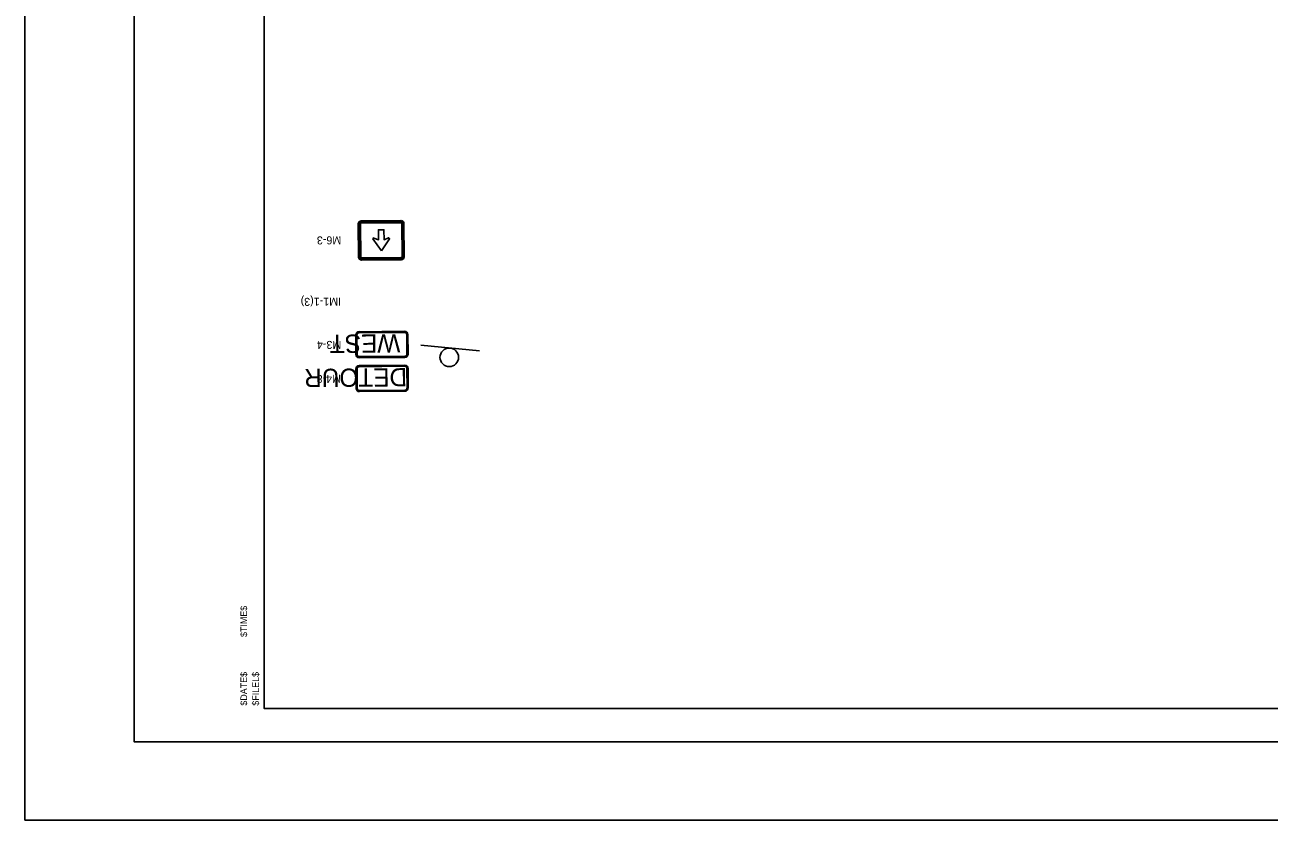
# Model space of a CAD drawing. Extents: x 2162123 to 2216123, y 180770 to 216770.
# Drawn here: x 2162123 to 2190113, y 180770 to 198666 of the extents above; entities that cross this region are included whole.
import ezdxf

# ---------------------------------------------------------------- set-up
doc = ezdxf.new("R2010")
doc.units = 0
for name, color, linetype in [('Default', 7, 'Continuous'), ('PR_Phasing_Detour_1', 7, 'Continuous'), ('SHT_Plot_Shape_Full', 7, 'Continuous'), ('SHT_Plot_Shape_Half', 7, 'Continuous'), ('SHT_Plot_Stamp', 7, 'Continuous'), ('SHT_Section_Layout_Block', 7, 'Continuous'), ('SHT_Sheet_Border', 7, 'Continuous')]:
    doc.layers.add(name, color=color, linetype=linetype)

# ---------------------------------------------------------------- blocks, each defined once
blk = doc.blocks.new('PRSIGN')
at = {"layer": 'Default'}
blk.add_line((20.04, 6.36), (-20.04, 6.36), dxfattribs=at)
blk.add_circle((0, 0), 6.35, dxfattribs=at)

msp = doc.modelspace()

# ---------------------------------------------------------------- linework, layer by layer
at = {"layer": 'PR_Phasing_Detour_1'}
for p, q in [((2170584, 194261), (2169689, 194253)), ((2169624, 194188), (2169630, 193439)), ((2169643, 194188), (2169649, 193439)), ((2169643, 194188), (2169649, 193439)), ((2169679, 193439), (2169673, 194188)), ((2169679, 193439), (2169673, 194188)), ((2170585, 194242), (2169689, 194235)), ((2170585, 194242), (2169689, 194235)), ((2169689, 194205), (2170585, 194212)), ((2169689, 194205), (2170585, 194212)), ((2170201, 194056), (2170076, 194055)), ((2170076, 194055), (2170078, 193829)), ((2170202, 193830), (2170201, 194056)), ((2170601, 194196), (2170607, 193447)), ((2170601, 194196), (2170607, 193447)), ((2170638, 193447), (2170632, 194196)), ((2170638, 193447), (2170632, 194196)), ((2170656, 193447), (2170650, 194196)), ((2169953, 193849), (2170142, 193579)), ((2170078, 193829), (2169973, 193869)), ((2170142, 193579), (2170327, 193852)), ((2170306, 193872), (2170202, 193830)), ((2170591, 193430), (2169695, 193423)), ((2170591, 193430), (2169695, 193423)), ((2169696, 193393), (2170591, 193400)), ((2169696, 193393), (2170591, 193400)), ((2169696, 193374), (2170592, 193382)), ((2170665, 191771), (2169639, 191762)), ((2170665, 191746), (2169640, 191738)), ((2169567, 191688), (2169570, 191249)), ((2169591, 191689), (2169595, 191249)), ((2170718, 191258), (2170714, 191698)), ((2170742, 191258), (2170739, 191698)), ((2169644, 191201), (2170670, 191209)), ((2169644, 191176), (2170670, 191184)), ((2169571, 190925), (2169574, 190485)), ((2169595, 190925), (2169599, 190485)), ((2170669, 191007), (2169643, 190999)), ((2170669, 190982), (2169644, 190974)), ((2170722, 190494), (2170718, 190934)), ((2170746, 190495), (2170743, 190934)), ((2169648, 190437), (2170673, 190445)), ((2169648, 190413), (2170674, 190421))]:
    msp.add_line(p, q, dxfattribs=at)
for points in [[(2170306, 193873), (2170202, 193831), (2170201, 194057), (2170076, 194056), (2170078, 193830), (2169973, 193870)], [(2169953, 193849), (2170142, 193580)], [(2170142, 193580), (2170327, 193852)]]:
    msp.add_lwpolyline(points, dxfattribs=at)
for centre, radius, start, end in [((2169689, 194189), 64.9, 90.4611, 180.4611), ((2170585, 194196), 64.9, 0.4611, 90.4611), ((2169689, 194189), 46.6, 90.4611, 180.4611), ((2169689, 194189), 46.6, 90.4611, 180.4611), ((2169689, 194189), 16.1, 90.4611, 180.4611), ((2169689, 194189), 16.1, 90.4611, 180.4611), ((2170585, 194196), 46.6, 0.4611, 90.4611), ((2170585, 194196), 46.6, 0.4611, 90.4611), ((2170585, 194196), 16.1, 0.4611, 90.4611), ((2170585, 194196), 16.1, 0.4611, 90.4611), ((2169973, 193850), 20.8, 90.4611, 180.4611), ((2169973, 193849), 20.8, 90.4611, 180.4611), ((2170306, 193852), 20.8, 0.4611, 90.4611), ((2170306, 193851), 20.8, 0.4611, 90.4611), ((2169695, 193439), 64.9, 180.4611, 270.4611), ((2169695, 193439), 46.6, 180.4611, 270.4611), ((2169695, 193439), 46.6, 180.4611, 270.4611), ((2169695, 193439), 16.1, 180.4611, 270.4611), ((2169695, 193439), 16.1, 180.4611, 270.4611), ((2170591, 193447), 46.6, 270.4611, 0.4611), ((2170591, 193447), 16.1, 270.4611, 0.4611), ((2170591, 193447), 46.6, 270.4611, 0.4611), ((2170591, 193447), 16.1, 270.4611, 0.4611), ((2170591, 193447), 64.9, 270.4611, 0.4611), ((2169640, 191689), 73.3, 90.4611, 180.4611), ((2169640, 191689), 48.8, 90.4611, 180.4611), ((2170666, 191697), 73.3, 0.4611, 90.4611), ((2170666, 191697), 48.8, 0.4611, 90.4611), ((2169644, 191249), 73.3, 180.4611, 270.4611), ((2169644, 191249), 48.8, 180.4611, 270.4611), ((2170669, 191258), 48.8, 270.4611, 0.4611), ((2170669, 191258), 73.3, 270.4611, 0.4611), ((2169644, 190925), 73.3, 90.4611, 180.4611), ((2169644, 190925), 48.8, 90.4611, 180.4611), ((2170670, 190934), 73.3, 0.4611, 90.4611), ((2170670, 190934), 48.8, 0.4611, 90.4611), ((2169647, 190486), 73.3, 180.4611, 270.4611), ((2169647, 190486), 48.8, 180.4611, 270.4611), ((2170673, 190494), 48.8, 270.4611, 0.4611), ((2170673, 190494), 73.3, 270.4611, 0.4611)]:
    msp.add_arc(centre, radius, start, end, dxfattribs=at)
at = {"layer": 'SHT_Plot_Shape_Full'}
msp.add_lwpolyline([(2162123, 216770), (2216123, 216770), (2216123, 180770), (2162123, 180770)], close=True, dxfattribs=at)
at = {"layer": 'SHT_Plot_Shape_Half'}
msp.add_lwpolyline([(2164579, 215532), (2215579, 215532), (2215579, 182532), (2164579, 182532)], close=True, dxfattribs=at)
at = {"layer": 'SHT_Section_Layout_Block'}
msp.add_lwpolyline([(2167504, 183282), (2167504, 214782), (2208387, 214782), (2208387, 211973), (2214628, 211973), (2214754, 185757), (2203354, 185757), (2203354, 183282)], close=True, dxfattribs=at)
at = {"layer": 'SHT_Sheet_Border'}
msp.add_lwpolyline([(2214754, 183282), (2167504, 183282), (2167504, 214782), (2214754, 214782)], close=True, dxfattribs=at)

# ---------------------------------------------------------------- block references
at = {"layer": 'PR_Phasing_Detour_1', "xscale": 32.99999999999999, "yscale": 33.00000000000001, "rotation": -5.478587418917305}
msp.add_blockref('PRSIGN', (2171670, 191184), dxfattribs=at)

# ---------------------------------------------------------------- texts
at = {"layer": 'PR_Phasing_Detour_1'}
for s, height, p in [('M6-3', 180, (2169240, 193909)), ('IM1-1(3)', 180, (2169236, 192529)), ('M3-4', 180, (2169241, 191556)), ('WEST', 410.3, (2170567, 191705)), ('DETOUR', 410.3, (2170720, 190942)), ('M4-8', 180, (2169232, 190792))]:
    msp.add_text(s, height=height, rotation=180.4611, dxfattribs=at).set_placement(p)
at = {"layer": 'SHT_Plot_Stamp'}
for s, p in [('$TIME$', (2167122, 184891)), ('$DATE$', (2167122, 183346)), ('$FILEL$', (2167388, 183346))]:
    msp.add_text(s, height=150, rotation=90, dxfattribs=at).set_placement(p)

doc.saveas('drawing.dxf')
